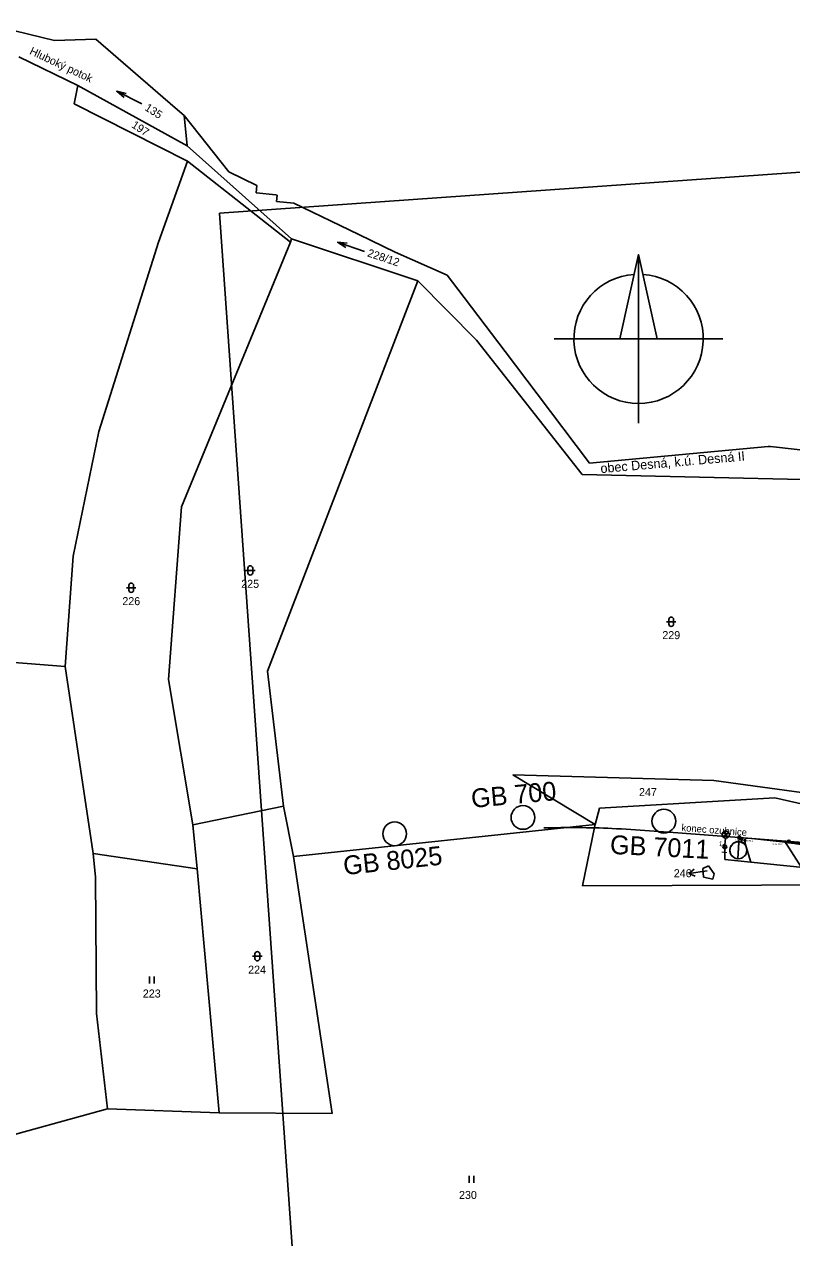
# Model space of a CAD drawing. Extents: x -670359 to -668019, y -978807 to -976674.
# Drawn here: x -669738.5 to -669575.5, y -977216.7 to -976959 of the extents above; entities that cross this region are included whole.
import ezdxf

# ---------------------------------------------------------------- set-up
doc = ezdxf.new("R2010")
doc.units = 0
for name, color, linetype in [('Hranice kat_území', 7, 'Continuous'), ('Hranice parcel', 7, 'Continuous'), ('Navazující stavba', 7, 'Continuous'), ('Názevy ku_obce_kraje', 7, 'Continuous'), ('Parcelní čísla', 7, 'Continuous'), ('Pop  PČ popisy', 7, 'Continuous'), ('Severka', 7, 'Continuous'), ('SO 01-86-01', 7, 'Continuous'), ('SO 11-10-01', 7, 'Continuous'), ('Související stavba', 7, 'Continuous'), ('Značky kultur', 7, 'Continuous'), ('ŽBP', 7, 'Continuous')]:
    doc.layers.add(name, color=color, linetype=linetype)

# ---------------------------------------------------------------- blocks, each defined once
blk = doc.blocks.new('20_01')
for p, q in [((-109.1, 0), (-24.2, 0)), ((0, 0), (-0.1, -109)), ((0, 0), (109.1, 0))]:
    blk.add_line(p, q)
for points in [[(0, 0), (-24.2, 0), (0.1, 109.1), (0, 0)], [(0, 0), (24.2, 0), (0.1, 109.1), (0, 0)], [(0, 0), (0.1, 109.1), (24.2, 0), (0, 0)]]:
    blk.add_lwpolyline(points)
blk.add_arc((0, 0), 83.7, 93.865, 86.101)
blk = doc.blocks.new('POINT_DISPLAY')
blk.add_line((0, 0), (0, 0))

msp = doc.modelspace()

# ---------------------------------------------------------------- linework, layer by layer
at = {"layer": 'Defpoints'}
for p in [(-669278.09, -976969.54), (-669676.69, -977287.4)]:
    msp.add_line(p, (-669697.04, -976999.11), dxfattribs=at)
at = {"layer": 'Hranice kat_území'}
for points in [[(-669746.37, -976958.97), (-669732.04, -976962.4)], [(-669732.04, -976962.4), (-669723.31, -976962.16)], [(-669723.31, -976962.16), (-669706.4, -976976.74)], [(-669706.4, -976976.74), (-669704.53, -976978.36)], [(-669704.53, -976978.36), (-669695.03, -976990.34)], [(-669695.03, -976990.34), (-669689.08, -976993.2)], [(-669689.08, -976993.2), (-669689.23, -976994.75)], [(-669689.23, -976994.75), (-669685.02, -976995.16)], [(-669685.02, -976995.16), (-669684.77, -976995.28)], [(-669684.77, -976995.28), (-669684.9, -976996.63)], [(-669684.9, -976996.63), (-669681.25, -976996.97)], [(-669681.25, -976996.97), (-669667.44, -977003.6)], [(-669659.72, -977007.36), (-669667.44, -977003.6)], [(-669659.72, -977007.36), (-669648.64, -977012.23)], [(-669648.64, -977012.23), (-669646.4, -977015.2)], [(-669646.4, -977015.2), (-669636.34, -977028.48)], [(-669636.34, -977028.48), (-669629.55, -977037.45)], [(-669618.41, -977052.18), (-669629.55, -977037.45)], [(-669618.41, -977052.18), (-669580.5, -977048.62)], [(-669580.5, -977048.62), (-669580.02, -977048.66)], [(-669578.74, -977048.77), (-669580.02, -977048.66)], [(-669578.74, -977048.77), (-669563.12, -977050.54)]]:
    msp.add_lwpolyline(points, dxfattribs=at)
at = {"layer": 'Hranice parcel'}
for points in [[(-669727.11, -976971.96), (-669739.62, -976965.89)], [(-669727.11, -976971.96), (-669727.89, -976975.88)], [(-669703.85, -976984.77), (-669727.11, -976971.96)], [(-669727.89, -976975.88), (-669703.83, -976988.05)], [(-669704.53, -976978.36), (-669703.85, -976984.77)], [(-669703.85, -976984.77), (-669681.75, -977004.54)], [(-669703.83, -976988.05), (-669709.98, -977005.27)], [(-669681.91, -977005.26), (-669703.83, -976988.05)], [(-669709.98, -977005.27), (-669722.63, -977045.46)], [(-669681.91, -977005.26), (-669705.11, -977061.49)], [(-669681.75, -977004.54), (-669681.91, -977005.26)], [(-669654.91, -977013.49), (-669681.75, -977004.54)], [(-669654.91, -977013.49), (-669686.85, -977096.39)], [(-669642.45, -977026.04), (-669654.91, -977013.49)], [(-669619.98, -977054.59), (-669642.45, -977026.04)], [(-669722.63, -977045.46), (-669728.09, -977071.94)], [(-669573.27, -977055.67), (-669619.98, -977054.59)], [(-669705.11, -977061.49), (-669707.88, -977098.11)], [(-669728.09, -977071.94), (-669729.8, -977095.37)], [(-669729.8, -977095.37), (-669786.45, -977090.91)], [(-669729.8, -977095.37), (-669723.83, -977135.05)], [(-669686.85, -977096.39), (-669683.42, -977125.06)], [(-669707.88, -977098.11), (-669702.67, -977129.01)], [(-669592.04, -977119.56), (-669634.75, -977118.37)], [(-669634.75, -977118.37), (-669617.2, -977128.92)], [(-669563.07, -977123.54), (-669592.04, -977119.56)], [(-669579.07, -977123.23), (-669616.33, -977125.45)], [(-669568.18, -977125.73), (-669579.07, -977123.23)], [(-669683.42, -977125.06), (-669702.67, -977129.01)], [(-669683.42, -977125.06), (-669681.28, -977135.75)], [(-669616.33, -977125.45), (-669617.2, -977128.92)], [(-669702.67, -977129.01), (-669701.74, -977138.35)], [(-669681.28, -977135.75), (-669617.2, -977128.92)], [(-669619.92, -977141.93), (-669617.27, -977129.22)], [(-669617.27, -977129.22), (-669617.2, -977128.92)], [(-669723.83, -977135.05), (-669723.32, -977140.08)], [(-669701.74, -977138.35), (-669723.83, -977135.05)], [(-669681.28, -977135.75), (-669673.07, -977190.28)], [(-669594.34, -977138.27), (-669593.14, -977137.7)], [(-669593.14, -977137.7), (-669591.94, -977139.37)], [(-669723.32, -977140.08), (-669723.17, -977169.08)], [(-669697.06, -977190.19), (-669701.74, -977138.35)], [(-669594.25, -977140.11), (-669594.34, -977138.27)], [(-669592.25, -977140.57), (-669594.25, -977140.11)], [(-669591.94, -977139.37), (-669592.25, -977140.57)], [(-669562.89, -977141.76), (-669619.92, -977141.93)], [(-669723.17, -977169.08), (-669720.82, -977189.29)], [(-669720.82, -977189.29), (-669745.97, -977196.23)], [(-669697.06, -977190.19), (-669720.82, -977189.29)], [(-669673.07, -977190.28), (-669697.06, -977190.19)]]:
    msp.add_lwpolyline(points, dxfattribs=at)
at = {"layer": 'Navazující stavba'}
msp.add_line((-669599.7, -977130.69), (-669586.62, -977131.71), dxfattribs=at)
msp.add_lwpolyline([(-669599.7, -977130.69), (-669600.7, -977130.61), (-669601.69, -977130.53), (-669602.69, -977130.46), (-669603.69, -977130.38), (-669604.69, -977130.31), (-669605.68, -977130.24), (-669606.68, -977130.17), (-669607.68, -977130.1), (-669608.68, -977130.03), (-669609.68, -977129.97), (-669610.67, -977129.91), (-669611.67, -977129.86), (-669612.67, -977129.81), (-669613.67, -977129.76)], dxfattribs=at)
msp.add_arc((-669622.21, -977329.58), 200, 87.5523, 91.6942, dxfattribs=at)
at = {"layer": 'Parcelní čísla'}
for p, q in [((-669597.35, -977139.34), (-669596.2, -977138.43)), ((-669593.47, -977138.77), (-669597.35, -977139.34)), ((-669595.98, -977139.88), (-669597.35, -977139.34))]:
    msp.add_line(p, q, dxfattribs=at)
at = {"layer": 'SO 01-86-01'}
for p, q in [((-669590.04, -977131.57), (-669588.95, -977130.54)), ((-669589.95, -977130.46), (-669589.04, -977131.65)), ((-669589.55, -977131.8), (-669589.67, -977133.3)), ((-669585.95, -977131.94), (-669586.33, -977131.94)), ((-669586.33, -977131.94), (-669586.33, -977132.22)), ((-669586.33, -977132.22), (-669585.95, -977132.22)), ((-669586.14, -977132.22), (-669586.1, -977132.67)), ((-669586.1, -977132.67), (-669585.38, -977132.95)), ((-669585.95, -977132.22), (-669585.95, -977131.94)), ((-669585.21, -977132.21), (-669585.58, -977132.21)), ((-669585.58, -977132.21), (-669585.58, -977132.49)), ((-669585.58, -977132.49), (-669585.21, -977132.49)), ((-669585.38, -977132.95), (-669585.39, -977132.49)), ((-669585.21, -977132.49), (-669585.21, -977132.21)), ((-669590.09, -977133.75), (-669589.59, -977133.31)), ((-669589.85, -977134.06), (-669589.31, -977133.6)), ((-669589.67, -977136.35), (-669589.71, -977133.74)), ((-669585.38, -977132.95), (-669584.14, -977136.93)), ((-669576.7, -977132.96), (-669573.41, -977138.03)), ((-669584.14, -977136.93), (-669589.67, -977136.35)), ((-669584.14, -977136.93), (-669559.19, -977139.53))]:
    msp.add_line(p, q, dxfattribs=at)
for centre, radius in [((-669589.49, -977131.06), 0.749), ((-669589.7, -977133.7), 0.4), ((-669576.7, -977132.96), 0.0916)]:
    msp.add_circle(centre, radius, dxfattribs=at)
at = {"layer": 'SO 11-10-01'}
for p, q in [((-669586.62, -977131.71), (-669586.97, -977136.19)), ((-669586.62, -977131.71), (-669559.57, -977133.81)), ((-669576.13, -977132.52), (-669559.81, -977135.63))]:
    msp.add_line(p, q, dxfattribs=at)
msp.add_lwpolyline([(-669586.97, -977136.19), (-669586.69, -977132.6), (-669586.69, -977132.6)], dxfattribs=at)
for centre, radius in [((-669586.83, -977134.4), 1.8), ((-669586.62, -977131.71), 0.3), ((-669576.13, -977132.52), 0.3)]:
    msp.add_circle(centre, radius, dxfattribs=at)
for centre, radius, start, end in [((-669586.83, -977134.4), 1.8, 85.5505, 265.549), ((-669601.37, -977321.13), 190, 79.209, 85.549)]:
    msp.add_arc(centre, radius, start, end, dxfattribs=at)
at = {"layer": 'Související stavba'}
msp.add_line((-669599.7, -977130.69), (-669586.62, -977131.71), dxfattribs=at)
msp.add_lwpolyline([(-669599.7, -977130.69), (-669600.7, -977130.61), (-669601.69, -977130.53), (-669602.69, -977130.46), (-669603.69, -977130.38), (-669604.69, -977130.31), (-669605.68, -977130.24), (-669606.68, -977130.17), (-669607.68, -977130.1), (-669608.68, -977130.03), (-669609.68, -977129.97), (-669610.67, -977129.91), (-669611.67, -977129.86), (-669612.67, -977129.81), (-669613.67, -977129.76)], dxfattribs=at)
msp.add_arc((-669622.21, -977329.58), 200, 87.5523, 91.6942, dxfattribs=at)
at = {"layer": 'Značky kultur'}
for p, q in [((-669713.49, -976975.89), (-669718.85, -976973.19)), ((-669666.25, -977007.23), (-669671.93, -977005.27)), ((-669691.47, -977074.96), (-669689.47, -977074.96)), ((-669690.97, -977074.46), (-669690.97, -977075.46)), ((-669689.97, -977074.46), (-669689.97, -977075.46)), ((-669716.26, -977078.14), (-669716.26, -977079.14)), ((-669715.26, -977078.14), (-669715.26, -977079.14)), ((-669716.76, -977078.64), (-669714.76, -977078.64)), ((-669602.08, -977085.86), (-669600.08, -977085.86)), ((-669601.58, -977085.36), (-669601.58, -977086.36)), ((-669600.58, -977085.36), (-669600.58, -977086.36)), ((-669689.98, -977156.91), (-669687.98, -977156.91)), ((-669689.48, -977156.41), (-669689.48, -977157.41)), ((-669688.48, -977156.41), (-669688.48, -977157.41)), ((-669711.86, -977161.22), (-669711.86, -977162.72)), ((-669710.86, -977162.72), (-669710.86, -977161.22)), ((-669643.98, -977203.56), (-669643.98, -977205.06)), ((-669642.98, -977205.06), (-669642.98, -977203.56))]:
    msp.add_line(p, q, dxfattribs=at)
for points in [[(-669717.29, -976974.54), (-669718.85, -976973.19), (-669716.84, -976973.64)], [(-669670.2, -977006.4), (-669671.93, -977005.27), (-669669.87, -977005.45)]]:
    msp.add_lwpolyline(points, dxfattribs=at)
for centre, start, end in [((-669690.47, -977074.46), 0, 180), ((-669690.47, -977075.46), 180, 0), ((-669715.76, -977078.14), 0, 180), ((-669715.76, -977079.14), 180, 0), ((-669601.08, -977085.36), 0, 180), ((-669601.08, -977086.36), 180, 0), ((-669688.98, -977156.41), 0, 180), ((-669688.98, -977157.41), 180, 0)]:
    msp.add_arc(centre, 0.5, start, end, dxfattribs=at)
at = {"layer": 'ŽBP'}
for centre in [(-669632.57, -977127.43), (-669602.65, -977128.21), (-669659.81, -977130.9)]:
    msp.add_circle(centre, 2.52, dxfattribs=at)

# ---------------------------------------------------------------- block references
at = {"layer": 'Severka', "xscale": 0.16404199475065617, "yscale": 0.16404199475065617}
msp.add_blockref('20_01', (-669608.02, -977025.78), dxfattribs=at)
at = {"layer": 'SO 01-86-01', "rotation": -4.450857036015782}
msp.add_blockref('POINT_DISPLAY', (-669589.7, -977133.7), dxfattribs=at)
at = {"layer": 'SO 11-10-01'}
msp.add_blockref('POINT_DISPLAY', (-669586.62, -977131.71), dxfattribs=at)
msp.add_blockref('POINT_DISPLAY', (-669586.62, -977131.71), dxfattribs=at)
msp.add_blockref('POINT_DISPLAY', (-669586.62, -977131.71), dxfattribs=at)
msp.add_blockref('POINT_DISPLAY', (-669586.62, -977131.71), dxfattribs=at)

# ---------------------------------------------------------------- texts
at = {"layer": 'Navazující stavba'}
msp.add_text('konec ozubnice', height=1.5, rotation=355.5591, dxfattribs=at).set_placement((-669598.95, -977130.3))
at = {"layer": 'Názevy ku_obce_kraje'}
msp.add_text('obec Desná, k.ú. Desná II', height=2, rotation=5.0172, dxfattribs=at).set_placement((-669616.03, -977054.31))
at = {"layer": 'Parcelní čísla'}
for s, rotation, p in [('135', 327.3247, (-669713.04, -976977.1)), ('197', 326.5237, (-669715.85, -976980.74)), ('228/12', 341.5185, (-669665.74, -977008.23))]:
    msp.add_text(s, height=1.7, rotation=rotation, dxfattribs=at).set_placement(p)
for s, height, p in [('225', 1.7, (-669692.4, -977078.66)), ('226', 1.7, (-669717.65, -977082.34)), ('229', 1.7, (-669602.97, -977089.56)), ('247', 1.7, (-669607.93, -977122.9)), ('246', 1.7, (-669600.54, -977140.12)), ('246', 0.1, (-669593.47, -977138.77)), ('224', 1.7, (-669690.94, -977160.61)), ('223', 1.7, (-669713.3, -977165.67)), ('230', 1.7, (-669646.15, -977208.45))]:
    msp.add_text(s, height=height, dxfattribs=at).set_placement(p)
at = {"layer": 'Pop  PČ popisy'}
msp.add_text('Hluboký potok', height=1.7, rotation=334.8, dxfattribs=at).set_placement((-669737.5, -976965.24))
at = {"layer": 'SO 01-86-01'}
msp.add_text('1', height=1, rotation=356.1, dxfattribs=at).set_placement((-669591, -977133.5))
for s, p in [('MX1.1', (-669587.54, -977132.4)), ('MX1.2', (-669585.06, -977132.56)), ('čidla EOV', (-669579.6, -977133.3))]:
    msp.add_text(s, height=0.35, dxfattribs=at).set_placement(p)
at = {"layer": 'SO 11-10-01'}
msp.add_text('1', height=2, rotation=355.5519, dxfattribs=at).set_placement((-669590.6, -977134.89))
at = {"layer": 'Související stavba'}
msp.add_text('konec ozubnice', height=1.5, rotation=355.5591, dxfattribs=at).set_placement((-669598.95, -977130.3))
at = {"layer": 'ŽBP'}
for s, rotation, p in [('GB 700', 5.3088, (-669643.39, -977125.41)), ('GB 7011', 357.049, (-669614.16, -977135.15)), ('GB 8025', 6.1153, (-669670.52, -977139.68))]:
    msp.add_text(s, height=4, rotation=rotation, dxfattribs=at).set_placement(p)

doc.saveas('drawing.dxf')
